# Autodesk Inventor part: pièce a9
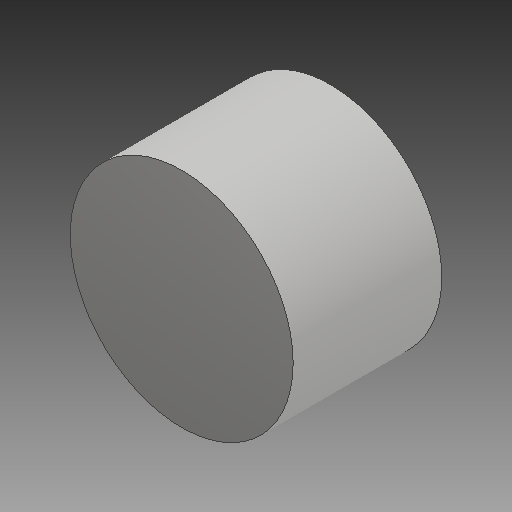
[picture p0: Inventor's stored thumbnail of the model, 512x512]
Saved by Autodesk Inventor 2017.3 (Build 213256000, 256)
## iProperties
Created: 2007-12
Part Number: pièce a9
Material: Générique
Document SubType Name: Modeling
Designer: ficho
Density: 1 g/cm^3
Appearance: Par défaut
Author: ficho
Sending System: SolidWorks 2009
Last Author: christophe
Last Saved: 2011-02-10
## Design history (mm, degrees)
extrude "Extrusion1"
node "Solide1"
